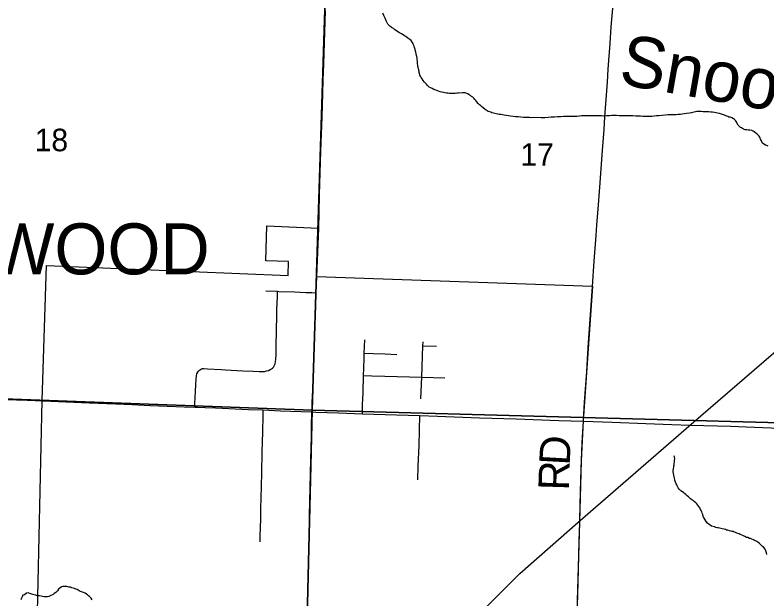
# Model space of a CAD drawing. Extents: x 2.4 to 73.1, y 4.5 to 25.6.
# Drawn here: x 30.776 to 31.475, y 22.974 to 23.516 of the extents above; entities that cross this region are included whole.
import ezdxf

# ---------------------------------------------------------------- set-up
doc = ezdxf.new("R2010")
doc.units = 0
for name, color, linetype in [('GM_X_City_Street', 7, 'Continuous'), ('GM_X_Corporation', 7, 'Continuous'), ('GM_X_Corporation_Text', 7, 'Continuous'), ('GM_X_Minor_River', 7, 'Continuous'), ('GM_X_Minor_River_Text', 7, 'Continuous'), ('GM_X_Rail_Line', 7, 'Continuous'), ('GM_X_Section', 7, 'Continuous'), ('GM_X_Section_Text', 7, 'Continuous'), ('GM_X_State_Route', 7, 'Continuous'), ('GM_X_Township_Road', 7, 'Continuous'), ('GM_X_Township_Road_Text', 7, 'Continuous'), ('GM_X_US_Route', 7, 'Continuous')]:
    doc.layers.add(name, color=color, linetype=linetype)

msp = doc.modelspace()

# ---------------------------------------------------------------- linework, layer by layer
at = {"layer": 'GM_X_City_Street'}
msp.add_line((31.15498, 23.20875), (31.16778, 23.20832), dxfattribs=at)
for points in [[(30.94325, 23.1518), (30.94334, 23.15456), (30.94337, 23.15518), (30.9439, 23.16636), (30.9442, 23.17289), (30.94451, 23.17786), (30.94478, 23.18096), (30.94523, 23.18276), (30.94589, 23.18417), (30.9466, 23.1852), (30.94743, 23.18613), (30.9484, 23.18689), (30.94954, 23.18736), (30.95046, 23.18753), (30.9517, 23.18761), (30.95513, 23.18749), (30.96784, 23.18664), (30.97157, 23.18639), (30.98772, 23.18554), (30.99736, 23.18514), (31.00295, 23.18487), (31.00606, 23.18483), (31.00792, 23.185), (31.00974, 23.18538), (31.01153, 23.18593), (31.01324, 23.18667), (31.0143, 23.18732), (31.01528, 23.18809), (31.01613, 23.18899), (31.01684, 23.19001), (31.01726, 23.19084), (31.0177, 23.192), (31.01813, 23.19382), (31.01845, 23.19629), (31.01867, 23.20033), (31.01872, 23.20717), (31.01897, 23.22427), (31.01933, 23.23577), (31.01951, 23.24354), (31.0196, 23.24758), (31.01988, 23.25565), (31.02001, 23.25937)], [(31.00922, 23.2598), (31.02001, 23.25937), (31.02124, 23.25932), (31.03586, 23.25876), (31.04642, 23.25841), (31.05202, 23.2582), (31.05597, 23.25805)], [(31.09892, 23.1457), (31.09898, 23.14889), (31.09908, 23.15385), (31.09951, 23.16532), (31.09995, 23.18105), (31.10012, 23.18797), (31.10049, 23.19728), (31.10063, 23.20207), (31.10105, 23.21436)], [(31.15324, 23.15939), (31.15394, 23.1796), (31.15498, 23.20875), (31.15512, 23.21257)], [(31.10063, 23.20207), (31.1088, 23.20172), (31.11999, 23.20129), (31.13095, 23.20083)], [(31.09995, 23.18105), (31.10754, 23.18088), (31.11955, 23.18053), (31.15394, 23.1796), (31.17536, 23.1789)], [(31.00378, 23.02674), (31.00399, 23.03296), (31.00426, 23.03948), (31.00442, 23.04849), (31.00464, 23.05812), (31.00492, 23.06682), (31.00538, 23.09044), (31.00578, 23.11034), (31.00623, 23.12867), (31.00661, 23.14388), (31.00674, 23.14918)], [(31.15038, 23.08434), (31.15039, 23.08465), (31.15068, 23.09705), (31.15143, 23.11626), (31.15183, 23.13052), (31.15207, 23.14399)]]:
    msp.add_lwpolyline(points, dxfattribs=at)
at = {"layer": 'GM_X_Corporation'}
msp.add_lwpolyline([(30.79022, 22.65272), (30.80151, 23.15784), (30.80559, 23.28341), (31.0299, 23.27419), (31.03034, 23.28721), (31.00903, 23.28777), (31.01013, 23.32018), (31.05817, 23.31797), (31.05636, 23.27324), (31.31243, 23.2641), (31.30394, 23.13894), (31.30214, 23.10178), (31.30053, 23.04493), (31.29335, 22.80535)], dxfattribs=at)
at = {"layer": 'GM_X_Minor_River'}
for points in [[(31.16003, 23.45006), (31.15909, 23.45083), (31.15835, 23.45179), (31.15722, 23.45295), (31.15629, 23.4541), (31.15517, 23.45526), (31.15424, 23.45679), (31.15331, 23.45795), (31.15276, 23.4591), (31.15221, 23.46025), (31.15185, 23.46158), (31.15167, 23.46253), (31.1515, 23.46349), (31.15132, 23.46463), (31.15115, 23.46558), (31.15078, 23.46654), (31.15061, 23.46768), (31.15044, 23.46863), (31.15026, 23.46958), (31.15009, 23.47073), (31.14992, 23.47187), (31.14993, 23.47282), (31.14977, 23.47472), (31.1496, 23.47605), (31.14925, 23.47739), (31.14907, 23.47853), (31.14891, 23.48005), (31.14855, 23.48139), (31.14765, 23.48482), (31.14729, 23.48597), (31.14693, 23.48711), (31.14638, 23.48845), (31.14583, 23.4896), (31.14509, 23.49094), (31.14416, 23.49229), (31.14303, 23.49325), (31.1419, 23.49403), (31.14096, 23.49462), (31.13908, 23.49598), (31.13795, 23.49656), (31.13664, 23.49753), (31.13513, 23.49851), (31.13343, 23.49949), (31.13174, 23.50046), (31.13042, 23.50124), (31.12891, 23.50222), (31.1276, 23.50357), (31.12572, 23.50455), (31.1244, 23.50571), (31.12347, 23.50667), (31.12253, 23.50764), (31.12142, 23.50936), (31.12106, 23.51051), (31.1205, 23.51166), (31.11996, 23.513), (31.11922, 23.51434), (31.11867, 23.51568), (31.11775, 23.51778)], [(31.34996, 23.42233), (31.34616, 23.42239), (31.34312, 23.42244), (31.34008, 23.42249), (31.33722, 23.42253), (31.33476, 23.42276), (31.33266, 23.4228), (31.33057, 23.42264), (31.32828, 23.42249), (31.32543, 23.42234), (31.32295, 23.42219), (31.32087, 23.42241), (31.31877, 23.42226), (31.31725, 23.42228), (31.31573, 23.42231), (31.31402, 23.42233), (31.31193, 23.42237), (31.30984, 23.4224), (31.30774, 23.42243), (31.30584, 23.42246), (31.30394, 23.42249), (31.30223, 23.42233), (31.30032, 23.42198), (31.29803, 23.42183), (31.29499, 23.42188), (31.29271, 23.42172), (31.29062, 23.42176), (31.28814, 23.4218), (31.28567, 23.42184), (31.28319, 23.4215), (31.28015, 23.42135), (31.2771, 23.42121), (31.27425, 23.42107), (31.27139, 23.42073), (31.26835, 23.42059), (31.26473, 23.42065), (31.25808, 23.42076), (31.25617, 23.4206), (31.2539, 23.42082), (31.25123, 23.42087), (31.24857, 23.42091), (31.24591, 23.42114), (31.24344, 23.42137), (31.24098, 23.4216), (31.23889, 23.42182), (31.23642, 23.42205), (31.23452, 23.42227), (31.23244, 23.42268), (31.23054, 23.42291), (31.22883, 23.42331), (31.22731, 23.42353), (31.2258, 23.42374), (31.22447, 23.42395), (31.22295, 23.42417), (31.22182, 23.42456), (31.22068, 23.42477), (31.21916, 23.42518), (31.21803, 23.42576), (31.2169, 23.42616), (31.21576, 23.42656), (31.21482, 23.42715), (31.21369, 23.42773), (31.21275, 23.42832), (31.21105, 23.42968), (31.20956, 23.43103), (31.20862, 23.43199), (31.20768, 23.43258), (31.20637, 23.43393), (31.20525, 23.43547), (31.20432, 23.43662), (31.20338, 23.43759), (31.20226, 23.43874), (31.20133, 23.43971), (31.2002, 23.44049), (31.19926, 23.44126), (31.19813, 23.44204), (31.19662, 23.44282), (31.19568, 23.44322), (31.19435, 23.44362), (31.19321, 23.44364), (31.19188, 23.44385), (31.18788, 23.44353), (31.18655, 23.44336), (31.18503, 23.4432), (31.18332, 23.44322), (31.18217, 23.44324), (31.18103, 23.44307), (31.1797, 23.44328), (31.17837, 23.4433), (31.17704, 23.44351), (31.17553, 23.44373), (31.1742, 23.44394), (31.17268, 23.44434), (31.17117, 23.44475), (31.16947, 23.44534), (31.16701, 23.44614), (31.16512, 23.44693), (31.16361, 23.44772), (31.16229, 23.44831), (31.16097, 23.44909), (31.16003, 23.45006)], [(31.4758, 23.39431), (31.47448, 23.3949), (31.47315, 23.39511), (31.47164, 23.39608), (31.47014, 23.39743), (31.4696, 23.39915), (31.46848, 23.40069), (31.46831, 23.40183), (31.46739, 23.40356), (31.46645, 23.40433), (31.46533, 23.40549), (31.46401, 23.40646), (31.46251, 23.40762), (31.46157, 23.40821), (31.46043, 23.40861), (31.45853, 23.40901), (31.45721, 23.40904), (31.45588, 23.40925), (31.45436, 23.40946), (31.45285, 23.41006), (31.45172, 23.41064), (31.45077, 23.41123), (31.44983, 23.41162), (31.44889, 23.4124), (31.44777, 23.41374), (31.44592, 23.417), (31.44517, 23.41797), (31.44424, 23.41893), (31.4433, 23.4197), (31.4418, 23.42068), (31.44047, 23.42108), (31.43914, 23.42129), (31.4382, 23.42168), (31.43631, 23.42229), (31.43442, 23.42327), (31.43234, 23.42406), (31.43044, 23.42447), (31.42874, 23.42487), (31.42722, 23.42509), (31.42571, 23.42549), (31.424, 23.42571), (31.42229, 23.42593), (31.42058, 23.42595), (31.41906, 23.42617), (31.41716, 23.4262), (31.41621, 23.42621), (31.41526, 23.42623), (31.41336, 23.42626), (31.41222, 23.42628), (31.41089, 23.4263), (31.40955, 23.42632), (31.40803, 23.42615), (31.4065, 23.4258), (31.40459, 23.42526), (31.40268, 23.42472), (31.39983, 23.42458), (31.39773, 23.42423), (31.39582, 23.42388), (31.39411, 23.42372), (31.3922, 23.42356), (31.39011, 23.4234), (31.38269, 23.42333), (31.38002, 23.42299), (31.37736, 23.42284), (31.37412, 23.42252), (31.37183, 23.42236), (31.36974, 23.42221), (31.36764, 23.42186), (31.36536, 23.42171), (31.36327, 23.42174), (31.36136, 23.42177), (31.35927, 23.4218), (31.35719, 23.42203), (31.3549, 23.42206), (31.35262, 23.4221), (31.34996, 23.42233)], [(31.47159, 23.02127), (31.47046, 23.02243), (31.46896, 23.02379), (31.46746, 23.02514), (31.46615, 23.02649), (31.46502, 23.02708), (31.46389, 23.02767), (31.46294, 23.02806), (31.462, 23.02846), (31.46049, 23.02905), (31.45917, 23.02964), (31.45822, 23.02985), (31.45671, 23.03063), (31.45557, 23.03084), (31.45387, 23.03163), (31.45217, 23.03241), (31.45048, 23.0332), (31.44953, 23.03359), (31.44858, 23.03399), (31.44764, 23.03438), (31.44651, 23.03478), (31.44537, 23.03537), (31.44405, 23.03577), (31.4431, 23.03616), (31.44216, 23.03637), (31.44121, 23.03658), (31.43988, 23.03698), (31.43818, 23.03738), (31.43704, 23.03759), (31.43591, 23.03799), (31.43477, 23.03839), (31.43288, 23.0388), (31.43174, 23.0392), (31.43041, 23.03941), (31.42928, 23.03981), (31.42814, 23.03982), (31.427, 23.04003), (31.42568, 23.04062), (31.42303, 23.04124), (31.42171, 23.04221), (31.42077, 23.04279), (31.41946, 23.04395), (31.41796, 23.0455), (31.41629, 23.04856), (31.41574, 23.04971), (31.41538, 23.05067), (31.41502, 23.052), (31.41447, 23.05334), (31.41411, 23.05468), (31.41356, 23.05582), (31.41281, 23.05679), (31.41226, 23.05812), (31.41133, 23.05947), (31.4104, 23.06081), (31.40947, 23.06197), (31.40853, 23.06293), (31.40684, 23.06429), (31.40591, 23.06507), (31.40478, 23.06584), (31.40365, 23.06662), (31.40252, 23.0674), (31.40158, 23.06836), (31.40046, 23.06933), (31.39933, 23.07049), (31.39802, 23.07146), (31.39689, 23.07243), (31.39558, 23.0734), (31.39445, 23.07418), (31.39295, 23.07553), (31.39202, 23.07688), (31.3911, 23.0786), (31.39073, 23.07956), (31.39017, 23.08051), (31.38963, 23.08204), (31.38909, 23.08395), (31.38873, 23.08567), (31.38838, 23.087), (31.38767, 23.09024), (31.3875, 23.09177), (31.38752, 23.09291), (31.38773, 23.09442), (31.38814, 23.09632), (31.38816, 23.09726), (31.38836, 23.09821), (31.38838, 23.09954), (31.38859, 23.10068), (31.38881, 23.10219), (31.38884, 23.10409), (31.38866, 23.10524), (31.3885, 23.10657), (31.3885, 23.10657), (31.38849, 23.10638)], [(31.47453, 23.01496), (31.47398, 23.01649), (31.47344, 23.0182), (31.47271, 23.01993), (31.47159, 23.02127)], [(30.84778, 22.97292), (30.84686, 22.97446), (30.84555, 22.97581), (30.84461, 22.97658), (30.84367, 22.97736), (30.84254, 22.97814), (30.84141, 22.9791), (30.8399, 22.97951), (30.83896, 22.9799), (30.83801, 22.9803), (30.83707, 22.98069), (30.83593, 22.98128), (30.83499, 22.98187), (30.83386, 22.98227), (30.83272, 22.98266), (30.83159, 22.98325), (30.83026, 22.98365), (30.82913, 22.98405), (30.82762, 22.98465), (30.82629, 22.98467), (30.82534, 22.98487), (30.82439, 22.98508), (30.82287, 22.98529), (30.82173, 22.98531), (30.82078, 22.98532), (30.81963, 22.98477), (30.81829, 22.98404), (30.81656, 22.98273), (30.81558, 22.98123), (30.81404, 22.97973), (30.81269, 22.97862), (30.81173, 22.97787), (30.80885, 22.9764), (30.8077, 22.97604), (30.80637, 22.97568), (30.80484, 22.97551), (30.80332, 22.97573), (30.80181, 22.97594), (30.80048, 22.97615), (30.79896, 22.97637), (30.79668, 22.97659), (30.79555, 22.97699), (30.79403, 22.9774), (30.79289, 22.97761), (30.79195, 22.978), (30.791, 22.9784), (30.79006, 22.97879), (30.78835, 22.9792), (30.78683, 22.97903), (30.78491, 22.97754), (30.78356, 22.977), (30.78278, 22.97568), (30.78199, 22.97379), (30.7816, 22.97285)]]:
    msp.add_lwpolyline(points, dxfattribs=at)
at = {"layer": 'GM_X_Rail_Line'}
msp.add_lwpolyline([(31.15082, 22.77929), (31.15301, 22.81783), (31.15606, 22.85087), (31.16518, 22.8839), (31.17561, 22.90346), (31.19386, 22.93867), (31.21341, 22.96562), (31.24513, 22.99735), (31.29901, 23.04472), (31.40415, 23.136), (31.55493, 23.26596), (31.68962, 23.38201), (31.70917, 23.39809), (31.72699, 23.41504), (31.75132, 23.44547), (31.77261, 23.48241), (31.78825, 23.52023), (31.79738, 23.55717), (31.80129, 23.60412), (31.80172, 23.63193), (31.80563, 23.95097), (31.8065, 24.13048), (31.81302, 24.6325), (31.81433, 24.78522)], dxfattribs=at)
at = {"layer": 'GM_X_Section'}
for points in [[(30.56745, 23.66026), (31.06791, 23.649), (31.0521, 23.14884), (30.55466, 23.16723)], [(31.06791, 23.649), (31.56119, 23.63922), (31.55553, 23.13542), (31.0521, 23.14884)], [(30.55466, 23.16723), (31.0521, 23.14884), (31.04027, 22.64802), (30.5437, 22.66298), (30.55431, 23.16022)], [(31.55553, 23.13542), (31.53976, 22.6366), (31.28899, 22.63456), (31.04027, 22.64802), (31.0521, 23.14884)]]:
    msp.add_lwpolyline(points, close=True, dxfattribs=at)
at = {"layer": 'GM_X_State_Route'}
for points in [[(30.645, 23.16358), (30.651, 23.16336), (30.69506, 23.16159), (30.71242, 23.16095), (30.72896, 23.16037), (30.7473, 23.15965), (30.78768, 23.15818), (30.80194, 23.15755), (30.80243, 23.15753)], [(30.80243, 23.15753), (30.84519, 23.1559), (30.86972, 23.15476), (30.88495, 23.15412), (30.90172, 23.15341), (30.91757, 23.15282), (30.93341, 23.15215), (30.94325, 23.1518), (30.94584, 23.1517), (30.95282, 23.15141)], [(30.95282, 23.15141), (30.9623, 23.15101), (30.99305, 23.14975), (31.00674, 23.14918), (31.02287, 23.14849), (31.05201, 23.14733)], [(31.05201, 23.14733), (31.05549, 23.14719), (31.07662, 23.14652), (31.09892, 23.1457), (31.13038, 23.14468), (31.15207, 23.14399), (31.16859, 23.14334), (31.20743, 23.14188), (31.24162, 23.14082), (31.28139, 23.13941), (31.30406, 23.13866)], [(31.30406, 23.13866), (31.33093, 23.13774), (31.362, 23.1367), (31.38622, 23.13579), (31.40331, 23.13511), (31.44091, 23.134), (31.45519, 23.1335), (31.48626, 23.13232)]]:
    msp.add_lwpolyline(points, dxfattribs=at)
at = {"layer": 'GM_X_Township_Road'}
for points in [[(31.31254, 23.26383), (31.31421, 23.28736), (31.3159, 23.31123), (31.31663, 23.32115), (31.31769, 23.33572), (31.31932, 23.35616), (31.3218, 23.39026), (31.32325, 23.40979), (31.32406, 23.42158), (31.32638, 23.45351), (31.3272, 23.4656), (31.32886, 23.48948), (31.32997, 23.50498), (31.33125, 23.52202), (31.33411, 23.55983), (31.33623, 23.58866), (31.33878, 23.62338), (31.33901, 23.62729), (31.3392, 23.63064), (31.33941, 23.6339), (31.33958, 23.63704), (31.3397, 23.64138), (31.33969, 23.64185)], [(31.30406, 23.13866), (31.30441, 23.14524), (31.30509, 23.15642), (31.3071, 23.18467), (31.30785, 23.19647), (31.30895, 23.21168), (31.31079, 23.23744), (31.31254, 23.26383)], [(31.30064, 23.04436), (31.30072, 23.04741), (31.30102, 23.06047), (31.30136, 23.07321), (31.30196, 23.09434), (31.30297, 23.1186), (31.30406, 23.13866)], [(31.29228, 22.80273), (31.29294, 22.80364), (31.29328, 22.80436), (31.29339, 22.80466), (31.29347, 22.80507), (31.29372, 22.82464), (31.29386, 22.83336), (31.29443, 22.84889), (31.29496, 22.86101), (31.29574, 22.87777), (31.29609, 22.88926), (31.29689, 22.91381), (31.2976, 22.9368), (31.29787, 22.94425), (31.29857, 22.96725), (31.29918, 22.989), (31.29991, 23.01385), (31.30022, 23.02753), (31.30064, 23.04436)]]:
    msp.add_lwpolyline(points, dxfattribs=at)
at = {"layer": 'GM_X_US_Route'}
for points in [[(31.05829, 23.3177), (31.05856, 23.33265), (31.05912, 23.34912), (31.0597, 23.36931), (31.06033, 23.3892), (31.06147, 23.42181), (31.06225, 23.44294), (31.06254, 23.45569), (31.06299, 23.47028), (31.0647, 23.52)], [(31.05648, 23.27296), (31.05669, 23.28046), (31.05829, 23.3177)], [(31.05201, 23.14733), (31.05206, 23.14925), (31.05229, 23.15608), (31.05274, 23.16757), (31.05341, 23.18496), (31.05394, 23.19862), (31.05427, 23.2095), (31.05481, 23.2244), (31.05529, 23.23651), (31.05592, 23.25671), (31.05597, 23.25805), (31.05648, 23.27296)], [(31.04589, 22.8586), (31.0462, 22.87246), (31.04696, 22.90507), (31.04707, 22.91128), (31.04739, 22.93304), (31.04757, 22.94484), (31.04791, 22.95757), (31.04802, 22.96138), (31.04828, 22.97123), (31.04843, 22.97993), (31.04883, 22.99795), (31.0493, 23.02126), (31.04983, 23.0514), (31.05009, 23.06382), (31.05092, 23.10328), (31.05145, 23.1244), (31.05166, 23.13372), (31.05201, 23.14733)]]:
    msp.add_lwpolyline(points, dxfattribs=at)

# ---------------------------------------------------------------- texts
at = {"layer": 'GM_X_Corporation_Text'}
msp.add_text('SHERWOOD', height=0.047348, rotation=0.00001, dxfattribs=at).set_placement((30.57715, 23.27513))
at = {"layer": 'GM_X_Minor_River_Text'}
msp.add_text('Snooks', height=0.04737, rotation=350.04921, dxfattribs=at).set_placement((31.3357, 23.45217))
at = {"layer": 'GM_X_Section_Text'}
for s, p in [('18', (30.79445, 23.38949)), ('17', (31.24549, 23.376))]:
    msp.add_text(s, height=0.020928, rotation=0.00001, dxfattribs=at).set_placement(p)
at = {"layer": 'GM_X_Township_Road_Text'}
for s, rotation, p in [('D', 86.84562, (31.29125, 23.09733)), ('R', 88.30199, (31.29057, 23.0742))]:
    msp.add_text(s, height=0.02841, rotation=rotation, dxfattribs=at).set_placement(p)

doc.saveas('drawing.dxf')
